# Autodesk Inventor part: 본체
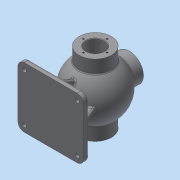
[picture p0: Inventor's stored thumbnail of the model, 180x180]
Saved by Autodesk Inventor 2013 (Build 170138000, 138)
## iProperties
Created: 2018-06
Part Number: 본체
Material: 일반
Document SubType Name: Modeling
Designer: Administrator
Density: 1 g/cm^3
Author: Administrator
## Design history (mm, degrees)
sketch "스케치2"
  geometry: L1 (0, 68)-(0, -68); L2 (0, 68)-(31, 68); L3 (31, -68)-(0, -68); L4 (31, 68)-(31, 42.988); L5 (31, -42.988)-(31, -68); L6 (17.5, 68)-(17.5, 39.278); L7 (17.5, -39.278)-(17.5, -68); A1 r 53 centre (0, 0) between (31, -42.988) and (31, 42.988); A2 r 43 centre (0, 0) between (17.5, -39.278) and (17.5, 39.278); 2 further points
  constraints: 14 end point, 5 perpendicular, 4 point on circle, 3 coincident, 2 centre point, 2 collinear, 2 point on line, 1 midpoint, 1 parallel, 1 vertical
  dimensions: "d4" = 106 diameter of A1; "d5" = 136 distance of L1.start L1.end; "d8" = 62 diameter of L4 L1; "d9" = 86 diameter of A2; "d10" = 35 diameter of L6 L1
revolve "회전1" sketch "스케치2" stored, may be unused: angle "d11" = 90 deg
node "작업 평면1"
sketch "스케치3"
  geometry: L1 (-62.5, -57.5)-(62.5, -57.5); L2 (62.5, -57.5)-(62.5, 57.5); L3 (62.5, 57.5)-(-62.5, 57.5); L4 (-62.5, 57.5)-(-62.5, -57.5); L5 (-62.5, -57.5)-(62.5, 57.5); L6 (62.5, -57.5)-(-62.5, 57.5); 1 further point
  constraints: 12 end point, 2 midpoint, 2 parallel, 1 horizontal, 1 perpendicular
  dimensions: "d13" = 125 distance of L3.end L2.end; "d14" = 115 distance of L2.end L1.end
extrude "돌출1" join sketch "스케치3" distance "d15" = 10; taper "d16" = 0 deg
fillet "모깎기1" dims "d17" = 12
hole "구멍1" diameter "d20" = 8; stored, may be unused: countersink angle "d24" = 90 deg, drill point angle "d26" = 0 deg; dims "d21" = 6, "d22" = 12, "d23" = 3, "d25" = 10, "d96" = 10, "d97" = 10
sketch "스케치4"
  geometry: L1 (-4, -4)-(4, -4); L2 (4, -4)-(4, 4); L3 (4, 4)-(-4, 4); L4 (-4, 4)-(-4, -4); L5 (-4, -4)-(4, 4); L6 (4, -4)-(-4, 4); 1 further point
  constraints: 12 end point, 2 midpoint, 2 parallel, 1 horizontal, 1 perpendicular
  dimensions: "d27" = 8 distance of L3.end L2.end; "d28" = 8 distance of L2.end L1.end
extrude "돌출2" join sketch "스케치4" stored distance "d29" = 10; taper "d30" = 0 deg
sketch "스케치5"
  geometry: L1 (52.5, -75)-(45.715, -58.208); L2 (62.5, -75)-(62.5, -85) reference; L3 (50.5, -75)-(62.5, -75) reference; 1 further point
  constraints: 2 end point, 1 point on line
  dimensions: "d31" = 22 deg angle of L2 L1; "d32" = 10 distance of L2.start L1.start
feature "리브1" sketch "스케치5" dims "d33" = 1, "d34" = 8, "d35" = 0, "d36" = 0, "d37" = 1, "d38" = 1
sketch "스케치6"
  geometry: L1 (-75, -47.5)-(-58.277, -40.743); L2 (-85, -57.5)-(-75, -57.5) reference; L3 (-75, -45.5)-(-75, -57.5) reference; 1 further point
  constraints: 2 end point, 1 point on line
  dimensions: "d39" = 22 deg angle of L2 L1; "d40" = 10 distance from line of L2 L1.start
feature "리브2" sketch "스케치6" dims "d41" = 1, "d42" = 8, "d43" = 0, "d44" = 0, "d45" = 1, "d46" = 1
fillet "모깎기2" dims "d47" = 3
fillet "모깎기3" dims "d48" = 3
fillet "모깎기4" dims "d49" = 3
node "작업 평면2"
sketch "스케치7"
  geometry: C1 r 27 at (0, 0); 1 further point
  constraints: 1 centre point, 1 coincident
  dimensions: "d51" = 54 diameter of C1
extrude "돌출3" join sketch "스케치7" stored distance "d52" = 10; taper "d53" = 0 deg
hole "구멍2" diameter "d56" = 26; stored, may be unused: countersink angle "d60" = 90 deg, drill point angle "d62" = 0 deg; dims "d54" = 10, "d55" = 10, "d57" = 6, "d58" = 4, "d59" = 2, "d61" = 8
chamfer "모따기1" distance "d63" = 1; stored, may be unused: second distance "d64" = 2, angle "d65" = 45 deg
sketch "스케치8"
  geometry: C1 r 27 at (0, 0) reference; 1 further point
  constraints: 1 vertical alignment
  dimensions: "d66" = 20 distance of C1.centre point (0, 20)
hole "구멍3" sketch "스케치8" at (0, 20) diameter "d67" = 3.242; stored, may be unused: countersink angle "d71" = 90 deg, drill point angle "d73" = 118 deg; dims "d68" = 9, "d69" = 4, "d70" = 2, "d72" = 11
node "작업 평면3"
sketch "스케치13"
  geometry: C1 r 31 at (0, 0) reference; 1 further point
  constraints: 1 vertical alignment
  dimensions: "d107" = 22.5 distance of C1.centre point (0, 22.5)
hole "구멍6" sketch "스케치13" at (0, 22.5) diameter "d108" = 3.242; stored, may be unused: countersink angle "d112" = 90 deg, drill point angle "d114" = 118 deg; dims "d109" = 12, "d110" = 4, "d111" = 2, "d113" = 15
sketch "스케치14"
  geometry: C1 r 31 at (0, 0) reference; 1 further point
  constraints: 1 vertical alignment
  dimensions: "d115" = 24 distance of C1.centre point (0, 24)
hole "구멍7" sketch "스케치14" at (0, 24) diameter "d116" = 3.242; stored, may be unused: countersink angle "d120" = 90 deg, drill point angle "d122" = 118 deg; dims "d117" = 16, "d118" = 4, "d119" = 2, "d121" = 19
sketch "스케치11"
  geometry: L1 (0, -27)-(0, 27) reference; 2 further points
  constraints: 1 other
  dimensions: "d98" = 10 distance from line of L1 point (10, 0); "d99" = 27 vertical distance of L1.start point (10, 0)
feature "엠보싱1" sketch "스케치11" dims "d100" = 0.5, "d101" = 0
fillet "모깎기5" dims "d102" = 3
node "작업 평면4"
sketch "스케치12"
  geometry: C1 r 18.5 at (0, 0); 1 further point
  constraints: 1 centre point, 1 coincident
  dimensions: "d104" = 37 diameter of C1
extrude "돌출4" cut sketch "스케치12" distance "d105" = 1.75; taper "d106" = 0 deg
node "솔리드1"
mirror "대칭1"
mirror "대칭2"
mirror "대칭3"
mirror "대칭4"
pattern_circular "원형 패턴1" dims angle "d75" = 360 deg
pattern_circular "원형 패턴3" dims angle "d124" = 360 deg
other parameters: "d6" = 62, "d12" = -85, "d103" = -16
